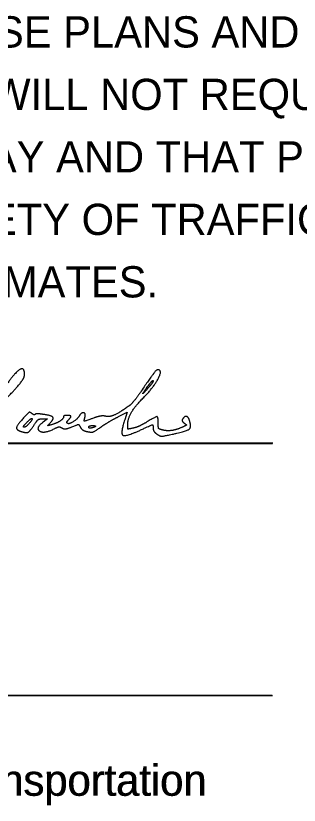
# Model space of a CAD drawing. Extents: x 0 to 82.7, y -0.2 to 22.
# Drawn here: x 26.874 to 28.147, y 7.305 to 10.842 of the extents above; entities that cross this region are included whole.
import ezdxf

# ---------------------------------------------------------------- set-up
doc = ezdxf.new("R2010")
doc.units = 0
for name, color, linetype in [('Default', 7, 'Continuous'), ('SH_Data', 7, 'Continuous'), ('SH_Text', 7, 'Continuous')]:
    doc.layers.add(name, color=color, linetype=linetype)

msp = doc.modelspace()

# ---------------------------------------------------------------- linework, layer by layer
at = {"layer": 'SH_Data'}
for p, q in [((24.5279, 8.9262), (28.0279, 8.9262)), ((24.5285, 8.928), (28.0285, 8.928)), ((24.5251, 7.797), (28.0251, 7.797)), ((24.5279, 7.7968), (28.0279, 7.7968))]:
    msp.add_line(p, q, dxfattribs=at)
at = {"layer": 'SH_Text'}
for points in [[(27.3361, 9.0462), (27.3748, 9.0655), (27.3633, 9.0308)], [(26.9953, 9.0359), (27.0162, 9.0357), (26.9979, 9.0217)]]:
    msp.add_lwpolyline(points, dxfattribs=at)
for points in [[(26.9136, 9.235), (26.9136, 9.2763), (26.8519, 9.2233), (26.8009, 9.1381)], [(26.8214, 9.1159), (26.8807, 9.1779), (26.9136, 9.2203), (26.9136, 9.235)], [(27.5198, 9.2537), (27.5102, 9.2597), (27.4902, 9.237), (27.4377, 9.1602)], [(27.4488, 9.1319), (27.4877, 9.1712), (27.5316, 9.2465), (27.5198, 9.2537)], [(27.4912, 9.2059), (27.4912, 9.202), (27.4805, 9.187), (27.4675, 9.1726)], [(27.4746, 9.191), (27.4837, 9.203), (27.4912, 9.2098), (27.4912, 9.2059)], [(27.4675, 9.1726), (27.443, 9.1453), (27.446, 9.1531), (27.4746, 9.191)], [(27.3772, 9.0101), (27.3772, 9.0371), (27.4097, 9.0923), (27.4488, 9.1319)], [(27.4377, 9.1602), (27.4172, 9.1303), (27.3909, 9.0991), (27.3793, 9.0909)], [(26.9463, 9.0601), (26.938, 9.067), (26.9303, 9.0628), (26.9095, 9.0401)], [(26.9614, 9.056), (26.9589, 9.0535), (26.952, 9.0553), (26.9463, 9.0601)], [(27.0006, 9.0555), (26.9816, 9.0584), (26.964, 9.0586), (26.9614, 9.056)], [(27.185, 9.0437), (27.1896, 9.0613), (27.1689, 9.0653), (27.159, 9.0487)], [(27.3793, 9.0909), (27.3384, 9.0621), (27.2937, 9.0433), (27.2765, 9.0477)], [(26.9095, 9.0401), (26.8798, 9.0077), (26.8759, 8.9862), (26.8984, 8.9791)], [(26.9211, 9.017), (26.9421, 9.0393), (26.9529, 9.0358), (26.9326, 9.0133)], [(26.9573, 9.0095), (26.9702, 9.0293), (26.9798, 9.036), (26.9953, 9.0359)], [(26.9979, 9.0217), (26.9602, 8.9927), (27.0039, 8.9688), (27.0504, 8.993)], [(27.0257, 9.0139), (27.0458, 9.0351), (27.0368, 9.0501), (27.0006, 9.0555)], [(27.0884, 9.0445), (27.0884, 9.0359), (27.0597, 9.0171), (27.0352, 9.0097)], [(27.1036, 9.0513), (27.0952, 9.0513), (27.0884, 9.0482), (27.0884, 9.0445)], [(27.1098, 9.0301), (27.1231, 9.0434), (27.1207, 9.0513), (27.1036, 9.0513)], [(27.1057, 9.0162), (27.103, 9.0189), (27.1048, 9.0252), (27.1098, 9.0301)], [(27.159, 9.0487), (27.1503, 9.0339), (27.1116, 9.0103), (27.1057, 9.0162)], [(27.2261, 9.0402), (27.1834, 9.0251), (27.1802, 9.0254), (27.185, 9.0437)], [(27.2765, 9.0477), (27.2671, 9.05), (27.2444, 9.0467), (27.2261, 9.0402)], [(27.2582, 9.0003), (27.2797, 9.015), (27.3148, 9.0356), (27.3361, 9.0462)], [(27.3633, 9.0308), (27.3433, 8.9699), (27.3672, 8.955), (27.4351, 8.9861)], [(27.4631, 9.0219), (27.443, 9.0097), (27.4155, 8.9973), (27.4019, 8.9945)], [(27.514, 9.013), (27.514, 9.0451), (27.5041, 9.0468), (27.4631, 9.0219)], [(27.5824, 8.968), (27.6438, 8.9816), (27.664, 8.9988), (27.6542, 9.0295)], [(27.6235, 9.0349), (27.6205, 9.0301), (27.6236, 9.0221), (27.6305, 9.0171)], [(27.6542, 9.0295), (27.6492, 9.0453), (27.6318, 9.0484), (27.6235, 9.0349)], [(26.8984, 8.9791), (26.9217, 8.9717), (26.9385, 8.9804), (26.9573, 9.0095)], [(26.9111, 8.9981), (26.9068, 8.9981), (26.9113, 9.0066), (26.9211, 9.017)], [(26.9326, 9.0133), (26.925, 9.0049), (26.9153, 8.9981), (26.9111, 8.9981)], [(27.0352, 9.0097), (27.0196, 9.005), (27.0179, 9.0058), (27.0257, 9.0139)], [(27.0504, 8.993), (27.0636, 8.9998), (27.0732, 9.0005), (27.082, 8.9952)], [(27.082, 8.9952), (27.0909, 8.9899), (27.1038, 8.9912), (27.1258, 8.9999)], [(27.1258, 8.9999), (27.1552, 9.0114), (27.1573, 9.0113), (27.1644, 8.9981)], [(27.1644, 8.9981), (27.1685, 8.9904), (27.1825, 8.9818), (27.1954, 8.9789)], [(27.1954, 8.9789), (27.2148, 8.9747), (27.2261, 8.9785), (27.2582, 9.0003)], [(27.2024, 8.9988), (27.2024, 9.0026), (27.2092, 9.0057), (27.2176, 9.0057)], [(27.2176, 8.9959), (27.2092, 8.9937), (27.2024, 8.995), (27.2024, 8.9988)], [(27.2176, 9.0057), (27.2259, 9.0057), (27.2328, 9.0044), (27.2328, 9.0027)], [(27.2328, 9.0027), (27.2328, 9.0011), (27.2259, 8.998), (27.2176, 8.9959)], [(27.4019, 8.9945), (27.3787, 8.9896), (27.3772, 8.9906), (27.3772, 9.0101)], [(27.4351, 8.9861), (27.4852, 9.0091), (27.4912, 9.0098), (27.4912, 8.9932)], [(27.4912, 8.9932), (27.4912, 8.9863), (27.4972, 8.9762), (27.5045, 8.9706)], [(27.533, 8.986), (27.5181, 8.9897), (27.514, 8.9956), (27.514, 9.013)], [(27.6247, 8.9997), (27.5969, 8.987), (27.5542, 8.9806), (27.533, 8.986)], [(27.6305, 9.0171), (27.6416, 9.0089), (27.641, 9.0071), (27.6247, 8.9997)], [(27.5045, 8.9706), (27.5204, 8.9585), (27.537, 8.958), (27.5824, 8.968)]]:
    msp.add_open_spline(points, degree=2, dxfattribs=at)

# ---------------------------------------------------------------- texts
at = {"layer": 'Default'}
for s, p in [('I HEREBY APPROVE THESE PLANS AND DECLARE THAT THE MAKING', (24.5279, 10.7)), ('OF THIS IMPROVEMENT WILL NOT REQUIRE THE CLOSING TO', (24.5279, 10.42)), ('TRAFFIC OF THE HIGHWAY AND THAT PROVISIONS FOR THE', (24.5279, 10.14)), ('MAINTENANCE AND SAFETY OF TRAFFIC WILL BE AS SET FORTH', (24.5279, 9.86)), ('ON THE PLANS AND ESTIMATES.', (24.5279, 9.58))]:
    msp.add_text(s, height=0.14, dxfattribs=at).set_placement(p)
at = {"layer": 'SH_Text'}
for p in [(24.5251, 7.347), (24.5279, 7.3468)]:
    msp.add_text('Director, Department of Transportation', height=0.14, dxfattribs=at).set_placement(p)

doc.saveas('drawing.dxf')
